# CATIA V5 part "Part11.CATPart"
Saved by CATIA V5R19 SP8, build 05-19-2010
Part number: Arc
Property "epaisseur_tige": 10 mm
Bounding box of the stored display mesh (mm): x -10 to 10, y 1600.014 to 2140.014, z -499.983 to 269.819
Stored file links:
  G:\EU_thinkMotion\CFAO_2010\MMS_groupe1\MMS_groupe1\OK\ppiault\piault\piault_cfao\Part11.CATPart
  D:\Catia\Finaltest.CATProduct
  G:\Catia Projet\CFAO2\Product2.CATProduct
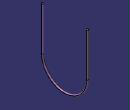
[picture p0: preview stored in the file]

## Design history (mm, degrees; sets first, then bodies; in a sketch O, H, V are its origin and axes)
Parameters
  epaisseur_tige = 10 mm
External parameters (linked from other documents)
  External.DiametreRabatteur = 400 mm
Body1 (main body)
  Sketch1 on yz-plane, origin (0, 0, 0), H (0, 1, 0), V (0, 0, 1)
    arc A1 centre (1870.014, -230.1811) radius 260 from (1610.014, -230.1811) to (2130.014, -230.1811) ccw
    line L1 (1610.014, 269.8189) -> (1610.014, -230.1811)
    point P2 (1610.014, -230.1811)
    point P3 (1610.014, 269.8189)
    line L2 (2130.014, 269.8189) -> (2130.014, -230.1811)
    point P6 (1610.014, -230.1811)
    length L2 = 500 {= External.DiametreRabatteur +100mm}
    length L1 = 500 {= External.DiametreRabatteur   +100mm}
    radius A1 = 260 {= 0.65*External.DiametreRabatteur}
    coincidence: P2 A1, L1 P6
    vertical: L2 V, L1 V
    tangency: A1 L2, A1 L1
  Sketch2 on xy-plane, origin (0, 0, 0), H (1, 0, 0), V (0, 1, 0)
    circle A1 centre (0, 1610.014) radius 10
    point P1 (0, 1610.014)
    reference projected point E1 (0, 1610.014) from Sketch1.P3
    radius A1 = 10 {= epaisseur_tige}
    coincidence: E1 P1
  Sweep1: type Unspec, Profile Sketch2, Guide Sketch1
  Set1
    CloseSurface1: CloseElement Sweep1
